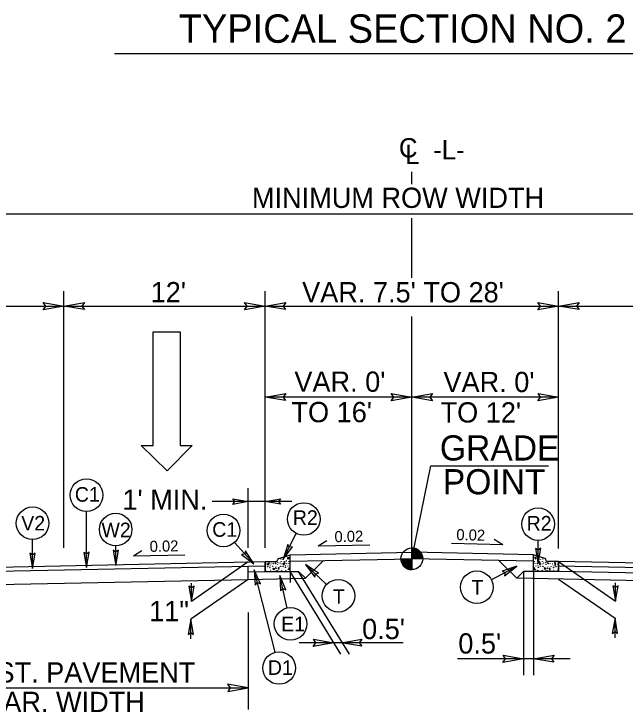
# Model space of a CAD drawing. Extents: x 3025871 to 3026431, y 707165 to 707825.
# Drawn here: x 3026150.34 to 3026186.78, y 707594.23 to 707635.86 of the extents above; entities that cross this region are included whole.
import ezdxf

# ---------------------------------------------------------------- set-up
doc = ezdxf.new("R2010")
doc.units = 0
for name, color, linetype in [('Prop Drainage Structure Junction Box with Manhole CELL', 7, 'Continuous'), ('Prop Drainage Structure Junction Box with Manhole Label', 7, 'Continuous'), ('Prop Drainage Structure Junction Box with Slab Lid CELL', 7, 'Continuous'), ('Prop Drainage Structure Junction Box with Slab Lid Label', 7, 'Continuous'), ('Prop Drainage Structure Junction Box with Slab Lid TB 840 34 CELL', 7, 'Continuous'), ('Prop Drainage Structure Plot Symbol 20 Scale', 7, 'Continuous'), ('Prop Drainage Structure Plot Symbol 50 Scale', 7, 'Continuous'), ('Prop Pavement Schedule Description CELL', 7, 'Continuous'), ('Sheet Data Field CELL', 7, 'Continuous'), ('Sheet Sticker Incomplete CELL', 7, 'Continuous'), ('Sheet Typical CELL', 7, 'Continuous'), ('Typical Arrow Superelevation CELL', 7, 'Continuous'), ('Typical Curb CELL', 7, 'Continuous'), ('Typical Grade Point Symbol CELL', 7, 'Continuous'), ('Typical Shoulder Slope CELL', 7, 'Continuous'), ('Typical Text Centerline CELL', 7, 'Continuous')]:
    doc.layers.add(name, color=color, linetype=linetype)

msp = doc.modelspace()

# ---------------------------------------------------------------- linework, layer by layer
at = {"layer": 'Prop Drainage Structure Junction Box with Manhole CELL'}
for p, q in [((3026166.809, 707602.606), (3026167.309, 707602.613)), ((3026167.714, 707602.204), (3026167.309, 707602.613)), ((3026180.321, 707602.206), (3026180.726, 707602.615)), ((3026181.314, 707602.606), (3026180.726, 707602.615)), ((3026164.312, 707602.136), (3026167.714, 707602.204)), ((3026210.43, 707601.603), (3026180.321, 707602.206))]:
    msp.add_line(p, q, dxfattribs=at)
at = {"layer": 'Prop Drainage Structure Junction Box with Manhole Label'}
for p, q in [((3026174.061, 707625.706), (3026174.061, 707626.456)), ((3026174.061, 707620.134), (3026174.061, 707623.693)), ((3026174.061, 707602.724), (3026174.061, 707617.815))]:
    msp.add_line(p, q, dxfattribs=at)
at = {"layer": 'Prop Drainage Structure Junction Box with Slab Lid CELL'}
for p, q in [((3026174.061, 707603.373), (3026174.061, 707604.022)), ((3026173.412, 707603.373), (3026174.061, 707603.373)), ((3026174.06, 707602.723), (3026174.061, 707603.373)), ((3026174.061, 707603.373), (3026174.06, 707602.723)), ((3026174.711, 707603.372), (3026174.061, 707603.373))]:
    msp.add_line(p, q, dxfattribs=at)
for points in [[(3026174.067, 707604.022), (3026174.067, 707604.022), (3026174.067, 707603.373)], [(3026174.08, 707604.022), (3026174.08, 707603.373)], [(3026174.093, 707604.021), (3026174.093, 707603.373)], [(3026174.106, 707604.021), (3026174.106, 707603.373)], [(3026174.119, 707604.019), (3026174.119, 707603.373)], [(3026174.132, 707604.018), (3026174.132, 707603.373)], [(3026174.145, 707604.016), (3026174.145, 707603.373)], [(3026174.158, 707604.015), (3026174.158, 707603.373)], [(3026174.171, 707604.013), (3026174.171, 707603.373)], [(3026174.184, 707604.01), (3026174.184, 707603.373)], [(3026174.197, 707604.007), (3026174.197, 707603.373)], [(3026174.21, 707604.005), (3026174.21, 707603.373)], [(3026174.223, 707604.002), (3026174.223, 707603.373)], [(3026174.236, 707603.997), (3026174.236, 707603.373)], [(3026174.249, 707603.994), (3026174.249, 707603.373)], [(3026174.262, 707603.99), (3026174.262, 707603.373)], [(3026174.275, 707603.986), (3026174.275, 707603.373)], [(3026174.288, 707603.982), (3026174.288, 707603.373)], [(3026174.301, 707603.976), (3026174.301, 707603.373)], [(3026174.314, 707603.97), (3026174.314, 707603.373)], [(3026174.327, 707603.964), (3026174.327, 707603.373)], [(3026174.34, 707603.958), (3026174.34, 707603.373)], [(3026174.353, 707603.953), (3026174.353, 707603.373)], [(3026174.366, 707603.945), (3026174.366, 707603.373)], [(3026174.379, 707603.938), (3026174.379, 707603.373)], [(3026174.392, 707603.931), (3026174.392, 707603.373)], [(3026174.405, 707603.924), (3026174.405, 707603.373)], [(3026174.418, 707603.915), (3026174.418, 707603.372)], [(3026174.431, 707603.906), (3026174.431, 707603.372)], [(3026174.444, 707603.896), (3026174.444, 707603.372)], [(3026174.457, 707603.888), (3026174.457, 707603.372)], [(3026174.47, 707603.878), (3026174.47, 707603.372)], [(3026174.483, 707603.866), (3026174.483, 707603.372)], [(3026174.496, 707603.854), (3026174.496, 707603.372)], [(3026174.509, 707603.843), (3026174.509, 707603.372)], [(3026174.522, 707603.83), (3026174.522, 707603.372)], [(3026174.535, 707603.817), (3026174.535, 707603.372)], [(3026174.548, 707603.802), (3026174.548, 707603.372)], [(3026174.561, 707603.787), (3026174.561, 707603.372)], [(3026174.574, 707603.771), (3026174.574, 707603.372)], [(3026174.587, 707603.753), (3026174.587, 707603.372)], [(3026174.6, 707603.735), (3026174.6, 707603.372)], [(3026174.613, 707603.714), (3026174.613, 707603.372)], [(3026174.626, 707603.693), (3026174.625, 707603.372)], [(3026174.639, 707603.67), (3026174.638, 707603.372)], [(3026174.652, 707603.642), (3026174.651, 707603.372)], [(3026173.415, 707603.373), (3026173.415, 707603.302)], [(3026173.428, 707603.373), (3026173.428, 707603.226)], [(3026173.441, 707603.373), (3026173.441, 707603.18)], [(3026173.454, 707603.373), (3026173.454, 707603.141)], [(3026173.467, 707603.373), (3026173.467, 707603.11)], [(3026173.48, 707603.373), (3026173.48, 707603.083)], [(3026173.493, 707603.373), (3026173.493, 707603.058)], [(3026173.506, 707603.373), (3026173.506, 707603.035)], [(3026173.519, 707603.373), (3026173.519, 707603.015)], [(3026173.532, 707603.373), (3026173.532, 707602.996)], [(3026173.545, 707603.373), (3026173.545, 707602.979)], [(3026173.558, 707603.373), (3026173.558, 707602.963)], [(3026173.571, 707603.373), (3026173.571, 707602.947)], [(3026173.584, 707603.373), (3026173.584, 707602.933)], [(3026173.597, 707603.373), (3026173.596, 707602.918)], [(3026173.61, 707603.373), (3026173.609, 707602.905)], [(3026173.623, 707603.373), (3026173.622, 707602.894)], [(3026173.636, 707603.373), (3026173.635, 707602.882)], [(3026173.649, 707603.373), (3026173.648, 707602.871)], [(3026173.662, 707603.373), (3026173.661, 707602.861)], [(3026173.675, 707603.373), (3026173.674, 707602.85)], [(3026173.688, 707603.373), (3026173.687, 707602.842)], [(3026173.701, 707603.373), (3026173.7, 707602.833)], [(3026173.714, 707603.373), (3026173.713, 707602.824)], [(3026173.727, 707603.373), (3026173.726, 707602.816)], [(3026173.74, 707603.373), (3026173.739, 707602.809)], [(3026173.752, 707603.373), (3026173.752, 707602.801)], [(3026173.765, 707603.373), (3026173.765, 707602.794)], [(3026173.778, 707603.373), (3026173.778, 707602.788)], [(3026173.791, 707603.373), (3026173.791, 707602.783)], [(3026173.804, 707603.373), (3026173.804, 707602.777)], [(3026173.817, 707603.373), (3026173.817, 707602.771)], [(3026173.83, 707603.373), (3026173.83, 707602.765)], [(3026173.843, 707603.373), (3026173.843, 707602.761)], [(3026173.856, 707603.373), (3026173.856, 707602.757)], [(3026173.869, 707603.373), (3026173.869, 707602.752)], [(3026173.882, 707603.373), (3026173.882, 707602.749)], [(3026173.895, 707603.373), (3026173.895, 707602.745)], [(3026173.908, 707603.373), (3026173.908, 707602.742)], [(3026173.921, 707603.373), (3026173.921, 707602.739)], [(3026173.934, 707603.373), (3026173.934, 707602.736)], [(3026173.947, 707603.373), (3026173.947, 707602.734)], [(3026173.96, 707603.373), (3026173.96, 707602.732)], [(3026173.973, 707603.373), (3026173.973, 707602.729)], [(3026173.986, 707603.373), (3026173.986, 707602.728)], [(3026173.999, 707603.373), (3026173.999, 707602.726)], [(3026174.012, 707603.373), (3026174.012, 707602.725)], [(3026174.025, 707603.373), (3026174.025, 707602.725)], [(3026174.038, 707603.373), (3026174.038, 707602.723)], [(3026174.051, 707603.373), (3026174.051, 707602.723), (3026174.051, 707602.723)], [(3026174.664, 707603.612), (3026174.664, 707603.372)], [(3026174.677, 707603.576), (3026174.677, 707603.372)], [(3026174.69, 707603.531), (3026174.69, 707603.372)], [(3026174.703, 707603.465), (3026174.703, 707603.372)]]:
    msp.add_lwpolyline(points, dxfattribs=at)
msp.add_circle((3026174.061, 707603.373), 0.649, dxfattribs=at)
for start, end in [(359.9709, 89.9709), (179.9709, 269.9709)]:
    msp.add_arc((3026174.061, 707603.373), 0.649, start, end, dxfattribs=at)
at = {"layer": 'Prop Drainage Structure Junction Box with Slab Lid Label'}
for p, q in [((3026166.812, 707603.614), (3026174.061, 707603.759)), ((3026181.311, 707603.614), (3026174.061, 707603.759)), ((3026166.812, 707603.227), (3026174.061, 707603.373)), ((3026181.311, 707603.227), (3026174.061, 707603.373))]:
    msp.add_line(p, q, dxfattribs=at)
at = {"layer": 'Prop Drainage Structure Junction Box with Slab Lid TB 840 34 CELL'}
for p, q in [((3026156.341, 707633.51), (3026191.781, 707633.51)), ((3026129.313, 707623.941), (3026223.827, 707623.941)), ((3026153.311, 707604.029), (3026153.311, 707619.333)), ((3026165.311, 707604.029), (3026165.311, 707619.333)), ((3026182.811, 707603.988), (3026182.811, 707619.333)), ((3026141.303, 707618.441), (3026206.819, 707618.441)), ((3026182.811, 707613.011), (3026165.311, 707613.011)), ((3026164.313, 707604.029), (3026164.313, 707607.582)), ((3026166.908, 707606.777), (3026162.148, 707606.777)), ((3026164.312, 707603.178), (3026160.926, 707600.829)), ((3026182.811, 707603.198), (3026186.197, 707600.849)), ((3026180.726, 707602.618), (3026180.726, 707596.42)), ((3026181.311, 707602.63), (3026181.311, 707596.42)), ((3026164.312, 707602.136), (3026160.891, 707599.763)), ((3026182.811, 707602.156), (3026186.178, 707599.82)), ((3026186.197, 707600.849), (3026186.197, 707601.941)), ((3026164.312, 707600.175), (3026164.312, 707594.384)), ((3026173.545, 707598.361), (3026167.347, 707598.359)), ((3026183.513, 707597.41), (3026176.792, 707597.41)), ((3026142.268, 707595.674), (3026164.202, 707595.674))]:
    msp.add_line(p, q, dxfattribs=at)
at = {"layer": 'Prop Drainage Structure Plot Symbol 20 Scale'}
msp.add_line((3026174.061, 707603.373), (3026175.186, 707608.918), dxfattribs=at)
at = {"layer": 'Prop Drainage Structure Plot Symbol 50 Scale'}
for p, q in [((3026166.062, 707603.291), (3026166.062, 707603.297)), ((3026166.126, 707603.386), (3026166.812, 707603.614)), ((3026166.665, 707603.442), (3026166.751, 707603.442)), ((3026166.67, 707603.356), (3026166.665, 707603.442)), ((3026166.751, 707603.442), (3026166.67, 707603.356)), ((3026166.812, 707602.614), (3026166.812, 707603.614)), ((3026181.311, 707602.614), (3026181.311, 707603.614)), ((3026181.997, 707603.386), (3026181.311, 707603.614)), ((3026181.458, 707603.442), (3026181.372, 707603.442)), ((3026181.372, 707603.442), (3026181.453, 707603.356)), ((3026181.453, 707603.356), (3026181.458, 707603.442)), ((3026182.061, 707603.291), (3026182.061, 707603.297)), ((3026165.311, 707603.198), (3026165.311, 707602.614)), ((3026165.311, 707603.198), (3026165.968, 707603.197)), ((3026165.311, 707602.614), (3026165.311, 707603.191)), ((3026165.465, 707603.066), (3026165.547, 707603.124)), ((3026165.505, 707602.975), (3026165.465, 707603.066)), ((3026165.547, 707603.124), (3026165.505, 707602.975)), ((3026165.804, 707602.808), (3026165.876, 707602.794)), ((3026165.84, 707602.685), (3026165.804, 707602.808)), ((3026165.876, 707602.794), (3026165.84, 707602.685)), ((3026166.158, 707602.85), (3026166.068, 707602.801)), ((3026166.068, 707602.801), (3026166.127, 707602.72)), ((3026166.127, 707602.72), (3026166.158, 707602.85)), ((3026166.384, 707603.081), (3026166.466, 707603.139)), ((3026166.425, 707602.99), (3026166.384, 707603.081)), ((3026166.466, 707603.139), (3026166.425, 707602.99)), ((3026166.724, 707602.824), (3026166.796, 707602.81)), ((3026166.759, 707602.701), (3026166.724, 707602.824)), ((3026166.796, 707602.81), (3026166.759, 707602.701)), ((3026181.399, 707602.824), (3026181.326, 707602.81)), ((3026181.326, 707602.81), (3026181.363, 707602.701)), ((3026181.363, 707602.701), (3026181.399, 707602.824)), ((3026181.656, 707603.139), (3026181.698, 707602.99)), ((3026181.738, 707603.081), (3026181.656, 707603.139)), ((3026181.698, 707602.99), (3026181.738, 707603.081)), ((3026181.964, 707602.85), (3026182.054, 707602.801)), ((3026181.996, 707602.72), (3026181.964, 707602.85)), ((3026182.054, 707602.801), (3026181.996, 707602.72)), ((3026182.811, 707603.198), (3026182.155, 707603.197)), ((3026182.318, 707602.808), (3026182.246, 707602.794)), ((3026182.246, 707602.794), (3026182.283, 707602.685)), ((3026182.283, 707602.685), (3026182.318, 707602.808)), ((3026182.576, 707603.124), (3026182.617, 707602.975)), ((3026182.658, 707603.066), (3026182.576, 707603.124)), ((3026182.617, 707602.975), (3026182.658, 707603.066)), ((3026182.811, 707603.198), (3026182.812, 707602.614)), ((3026182.812, 707602.614), (3026182.811, 707603.191)), ((3026165.311, 707602.614), (3026166.812, 707602.614)), ((3026182.812, 707602.614), (3026181.311, 707602.614))]:
    msp.add_line(p, q, dxfattribs=at)
for centre in [(3026166.249, 707603.361), (3026166.267, 707603.198), (3026166.385, 707603.338), (3026166.574, 707603.243), (3026166.602, 707603.528), (3026166.737, 707603.203), (3026181.385, 707603.203), (3026181.521, 707603.528), (3026181.548, 707603.243), (3026181.738, 707603.338), (3026181.855, 707603.198), (3026181.874, 707603.361), (3026165.32, 707602.907), (3026165.37, 707603.047), (3026165.465, 707602.903), (3026165.537, 707603.178), (3026165.6, 707602.839), (3026165.614, 707602.934), (3026165.659, 707603.065), (3026165.75, 707602.921), (3026165.808, 707603.079), (3026165.926, 707603.083), (3026165.942, 707603.113), (3026165.948, 707602.88), (3026165.964, 707602.801), (3026166.055, 707603.036), (3026166.077, 707603.135), (3026166.199, 707603.108), (3026166.24, 707602.923), (3026166.271, 707602.787), (3026166.29, 707603.063), (3026166.384, 707602.918), (3026166.457, 707603.194), (3026166.52, 707602.855), (3026166.534, 707602.95), (3026166.579, 707603.081), (3026166.669, 707602.936), (3026166.728, 707603.094), (3026181.394, 707603.094), (3026181.453, 707602.936), (3026181.544, 707603.081), (3026181.589, 707602.95), (3026181.602, 707602.855), (3026181.666, 707603.194), (3026181.738, 707602.918), (3026181.833, 707603.063), (3026181.851, 707602.787), (3026181.883, 707602.923), (3026181.923, 707603.108), (3026182.045, 707603.135), (3026182.068, 707603.036), (3026182.158, 707602.801), (3026182.174, 707602.88), (3026182.181, 707603.113), (3026182.197, 707603.083), (3026182.314, 707603.079), (3026182.373, 707602.921), (3026182.463, 707603.065), (3026182.509, 707602.934), (3026182.522, 707602.839), (3026182.585, 707603.178), (3026182.658, 707602.903), (3026182.753, 707603.047), (3026182.802, 707602.907), (3026165.352, 707602.772), (3026165.365, 707602.65), (3026165.627, 707602.668), (3026165.772, 707602.708), (3026165.964, 707602.647), (3026166.041, 707602.661), (3026166.285, 707602.665), (3026166.547, 707602.683), (3026166.692, 707602.724), (3026181.431, 707602.724), (3026181.575, 707602.683), (3026181.838, 707602.665), (3026182.082, 707602.661), (3026182.158, 707602.647), (3026182.35, 707602.708), (3026182.495, 707602.668), (3026182.757, 707602.65), (3026182.771, 707602.772)]:
    msp.add_circle(centre, 0.00635, dxfattribs=at)
for centre, radius, start, end in [((3026165.968, 707603.291), 0.0938, 269.9804, 359.9804), ((3026166.155, 707603.297), 0.0938, 108.4154, 179.9804), ((3026181.967, 707603.297), 0.0938, 0.0196, 71.5846), ((3026182.155, 707603.291), 0.0938, 180.0196, 270.0196), ((3026166.777, 707602.62), 0.00635, 25.7388, 152.9419), ((3026181.345, 707602.62), 0.00635, 27.0581, 154.2612)]:
    msp.add_arc(centre, radius, start, end, dxfattribs=at)
at = {"layer": 'Prop Pavement Schedule Description CELL'}
for p, q in [((3026141.303, 707602.717), (3026165.311, 707603.198)), ((3026141.303, 707602.467), (3026165.311, 707602.948)), ((3026164.312, 707602.136), (3026164.312, 707602.928)), ((3026206.819, 707602.717), (3026182.811, 707603.198)), ((3026182.811, 707602.948), (3026206.819, 707602.467)), ((3026164.309, 707602.594), (3026165.308, 707602.614)), ((3026206.819, 707602.134), (3026182.814, 707602.614)), ((3026142.298, 707601.696), (3026164.312, 707602.136))]:
    msp.add_line(p, q, dxfattribs=at)
at = {"layer": 'Sheet Data Field CELL'}
for p, q in [((3026158.648, 707610.134), (3026158.648, 707616.904)), ((3026158.648, 707616.904), (3026160.244, 707616.904)), ((3026160.244, 707616.904), (3026160.244, 707610.134)), ((3026159.471, 707608.61), (3026157.923, 707610.134)), ((3026157.923, 707610.134), (3026158.648, 707610.134)), ((3026160.97, 707610.134), (3026159.471, 707608.61)), ((3026160.244, 707610.134), (3026160.97, 707610.134))]:
    msp.add_line(p, q, dxfattribs=at)
at = {"layer": 'Sheet Sticker Incomplete CELL'}
for p, q in [((3026168.487, 707604.145), (3026169.002, 707604.456)), ((3026179.487, 707604.198), (3026178.974, 707604.512)), ((3026168.487, 707604.145), (3026171.555, 707604.206)), ((3026179.487, 707604.198), (3026176.42, 707604.275)), ((3026157.457, 707603.543), (3026157.972, 707603.855)), ((3026157.457, 707603.543), (3026160.524, 707603.605))]:
    msp.add_line(p, q, dxfattribs=at)
at = {"layer": 'Sheet Typical CELL'}
for p, q in [((3026167.714, 707602.204), (3026168.788, 707603.267)), ((3026180.321, 707602.206), (3026179.247, 707603.269))]:
    msp.add_line(p, q, dxfattribs=at)
at = {"layer": 'Typical Curb CELL'}
msp.add_line((3026166.812, 707602.606), (3026166.812, 707601.952), dxfattribs=at)
at = {"layer": 'Typical Grade Point Symbol CELL'}
for p, q in [((3026154.665, 707602.843), (3026154.663, 707606.192)), ((3026166.385, 707603.345), (3026167.174, 707604.878)), ((3026151.451, 707602.789), (3026151.45, 707604.514)), ((3026181.594, 707603.083), (3026181.593, 707604.464)), ((3026156.404, 707602.967), (3026156.404, 707604.136)), ((3026164.641, 707603.059), (3026163.486, 707604.339)), ((3026168.982, 707601.833), (3026167.732, 707603.021)), ((3026178.801, 707602.121), (3026180.33, 707602.919)), ((3026165.912, 707597.795), (3026164.66, 707602.719)), ((3026166.625, 707600.433), (3026166.197, 707602.376)), ((3026169.836, 707597.683), (3026166.809, 707602.604)), ((3026170.34, 707597.686), (3026167.309, 707602.613)), ((3026160.926, 707600.829), (3026160.925, 707601.921)), ((3026160.891, 707598.591), (3026160.891, 707599.763)), ((3026186.179, 707598.649), (3026186.178, 707599.82))]:
    msp.add_line(p, q, dxfattribs=at)
for centre in [(3026154.663, 707607.164), (3026167.62, 707605.741), (3026151.45, 707605.486), (3026181.593, 707605.436), (3026156.404, 707605.108), (3026162.835, 707605.062), (3026177.939, 707601.673), (3026169.686, 707601.163), (3026166.834, 707599.484), (3026166.152, 707596.853)]:
    msp.add_circle(centre, 0.972, dxfattribs=at)
at = {"layer": 'Typical Shoulder Slope CELL'}
msp.add_line((3026175.186, 707608.918), (3026182.212, 707608.916), dxfattribs=at)
at = {"layer": 'Typical Text Centerline CELL'}
for points in [[(3026152.087, 707618.652), (3026153.312, 707618.441), (3026152.08, 707618.223), (3026152.237, 707618.441)], [(3026154.536, 707618.23), (3026153.311, 707618.441), (3026154.543, 707618.659), (3026154.387, 707618.441)], [(3026164.087, 707618.652), (3026165.312, 707618.441), (3026164.08, 707618.223), (3026164.237, 707618.441)], [(3026166.536, 707618.23), (3026165.311, 707618.441), (3026166.543, 707618.659), (3026166.387, 707618.441)], [(3026181.585, 707618.652), (3026182.811, 707618.441), (3026181.579, 707618.223), (3026181.735, 707618.441)], [(3026184.035, 707618.23), (3026182.81, 707618.441), (3026184.042, 707618.659), (3026183.885, 707618.441)], [(3026166.536, 707612.8), (3026165.311, 707613.011), (3026166.543, 707613.228), (3026166.387, 707613.011)], [(3026172.837, 707613.221), (3026174.062, 707613.01), (3026172.83, 707612.793), (3026172.987, 707613.01)], [(3026175.286, 707612.799), (3026174.061, 707613.01), (3026175.293, 707613.228), (3026175.137, 707613.01)], [(3026181.586, 707613.222), (3026182.811, 707613.011), (3026181.579, 707612.793), (3026181.736, 707613.011)], [(3026163.393, 707606.935), (3026164.312, 707606.777), (3026163.388, 707606.613), (3026163.505, 707606.777)], [(3026166.23, 707606.618), (3026165.311, 707606.777), (3026166.235, 707606.94), (3026166.118, 707606.777)], [(3026166.662, 707604.225), (3026166.385, 707603.345), (3026166.947, 707604.084), (3026166.75, 707604.054)], [(3026151.293, 707603.699), (3026151.451, 707602.789), (3026151.612, 707603.704), (3026151.45, 707603.588)], [(3026154.508, 707603.753), (3026154.665, 707602.843), (3026154.826, 707603.758), (3026154.664, 707603.641)], [(3026156.247, 707603.877), (3026156.404, 707602.967), (3026156.566, 707603.882), (3026156.404, 707603.766)], [(3026163.915, 707603.629), (3026164.641, 707603.059), (3026164.148, 707603.846), (3026164.106, 707603.652)], [(3026181.436, 707603.992), (3026181.594, 707603.083), (3026181.755, 707603.997), (3026181.593, 707603.881)], [(3026168.499, 707602.508), (3026167.732, 707603.021), (3026168.283, 707602.273), (3026168.311, 707602.471)], [(3026179.596, 707602.359), (3026180.33, 707602.919), (3026179.445, 707602.639), (3026179.622, 707602.55)], [(3026165.036, 707601.876), (3026164.66, 707602.719), (3026164.729, 707601.793), (3026164.857, 707601.945)], [(3026166.546, 707601.522), (3026166.197, 707602.376), (3026166.236, 707601.448), (3026166.369, 707601.597)], [(3026160.769, 707601.739), (3026160.926, 707600.829), (3026161.087, 707601.744), (3026160.926, 707601.627)], [(3026186.04, 707601.759), (3026186.197, 707600.849), (3026186.358, 707601.764), (3026186.196, 707601.647)], [(3026161.048, 707598.853), (3026160.891, 707599.763), (3026160.73, 707598.848), (3026160.891, 707598.964)], [(3026186.335, 707598.911), (3026186.178, 707599.82), (3026186.017, 707598.905), (3026186.179, 707599.022)], [(3026168.195, 707598.57), (3026169.42, 707598.359), (3026168.188, 707598.141), (3026168.345, 707598.359)], [(3026171.081, 707598.148), (3026169.856, 707598.359), (3026171.088, 707598.577), (3026170.931, 707598.359)], [(3026179.502, 707597.621), (3026180.727, 707597.41), (3026179.495, 707597.192), (3026179.651, 707597.41)], [(3026182.536, 707597.199), (3026181.311, 707597.41), (3026182.543, 707597.628), (3026182.386, 707597.41)], [(3026163.087, 707595.463), (3026164.312, 707595.674), (3026163.08, 707595.892), (3026163.236, 707595.674)]]:
    msp.add_lwpolyline(points, close=True, dxfattribs=at)

# ---------------------------------------------------------------- texts
at = {"layer": 'Prop Drainage Structure Junction Box with Manhole Label'}
msp.add_text('C', height=1.152, dxfattribs=at).set_placement((3026173.29, 707627.306))
for s, height, p in [('-L-', 1.1523, (3026175.328, 707627.187)), ('L', 1.152, (3026173.672, 707626.912))]:
    msp.add_text(s, height=height, rotation=359.9469, dxfattribs=at).set_placement(p)
at = {"layer": 'Prop Drainage Structure Junction Box with Slab Lid TB 840 34 CELL'}
msp.add_text('TYPICAL SECTION NO. 2', height=1.69489, rotation=360, dxfattribs=at).set_placement((3026160.163, 707634.144))
for s, height, p in [('MINIMUM ROW WIDTH', 1.20892, (3026164.53, 707624.296)), ("12'", 1.2089, (3026158.491, 707618.667)), ("VAR. 7.5' TO 28'", 1.20892, (3026167.522, 707618.663)), ("VAR. 0' ", 1.2089, (3026167.058, 707613.328)), ("VAR. 0'", 1.2089, (3026175.948, 707613.31)), ("TO 16'", 1.2089, (3026166.886, 707611.514)), ("TO 12'", 1.2089, (3026175.776, 707611.496)), ("1' MIN.", 1.2089, (3026156.806, 707606.292)), ('11"', 1.2089, (3026158.399, 707599.648)), ("0.5'", 1.2089, (3026171.097, 707598.579)), ("0.5'", 1.2089, (3026176.834, 707597.715)), ('EXIST. PAVEMENT', 1.20892, (3026146.691, 707595.986)), ('VAR. WIDTH', 1.2089, (3026148.622, 707594.228))]:
    msp.add_text(s, height=height, dxfattribs=at).set_placement(p)
at = {"layer": 'Sheet Sticker Incomplete CELL'}
for s, rotation, p in [('0.02 ', 1.2029, (3026169.457, 707604.359)), ('0.02', 358.5679, (3026176.71, 707604.485)), ('0.02 ', 1.2029, (3026158.437, 707603.779))]:
    msp.add_text(s, height=0.6583, rotation=rotation, dxfattribs=at).set_placement(p)
at = {"layer": 'Typical Arrow Superelevation CELL'}
for s, p in [('C1', (3026153.97, 707606.775)), ('V2', (3026150.773, 707605.056)), ('R2', (3026180.907, 707605.053)), ('W2', (3026155.557, 707604.656)), ('C1', (3026162.161, 707604.682)), ('T', (3026177.615, 707601.235))]:
    msp.add_text(s, height=0.87, dxfattribs=at).set_placement(p)
for s, p in [('R2', (3026166.968, 707605.39)), ('T', (3026169.352, 707600.683)), ('E1', (3026166.274, 707599.047)), ('D1', (3026165.478, 707596.446))]:
    msp.add_text(s, height=0.87, rotation=360, dxfattribs=at).set_placement(p)
at = {"layer": 'Typical Shoulder Slope CELL'}
for s, p in [('GRADE', (3026175.733, 707609.231)), ('POINT', (3026175.907, 707607.215))]:
    msp.add_text(s, height=1.5, rotation=359.9804, dxfattribs=at).set_placement(p)

doc.saveas('drawing.dxf')
